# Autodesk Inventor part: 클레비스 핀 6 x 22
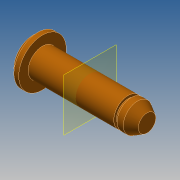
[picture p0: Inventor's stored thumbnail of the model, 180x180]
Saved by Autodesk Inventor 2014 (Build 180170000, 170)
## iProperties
IsCustomPart: 1
Created: 2017-08
Part Number: 클레비스 핀 6 x 22
Material: 강철
Description: 머리가 있는 클레비스 핀
Document SubType Name: Modeling
Standard: ISO 2341
Designer: mduedu
Standard Revision: Second edition 1986-11-01
Standards Organization: ISO
Language: ko-KR
Size Designation: B - 6 x 24
Categories: <MemberInstance><Categories><Category DisplayName="조임쇠" InternalName="e4da775c-781d-43d5-af7c-5136215cf5a6" Mnemonic="FSTN"><Category DisplayName="핀" InternalNa
Density: 7.85 g/cm^3
Appearance: 주황색
Author: mduedu
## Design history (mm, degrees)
sketch "스케치1"
  geometry: L1 (-2, 0)-(-2, 5); L2 (-2, 5)-(0, 5); L3 (0, 5)-(0, 3); L4 (0, 3)-(22, 3); L5 (22, 3)-(22, 0); L6 (-2, 0)-(22, 0); L7 (-7, 0)-(28, 0) reference; L8 (0, -1.96)-(0, 6.16) reference; C1 r 0.8 at (18.8, 0)
  constraints: 12 end point, 3 parallel, 2 collinear, 2 perpendicular, 1 centre point, 1 point on line, 1 vertical
  dimensions: "d0" = 6 diameter of L4 L6 (= NND); "d1" = 10 diameter of L2 L6 (= KOD); "d2" = 2 distance of L1.end L2.end (= KOH); "d3" = 22 distance of L3.end L4.end (= NLG); "d5" = 3.2 distance from line of L5 C1.centre (= DIST); "d6" = 1.6 diameter of C1 (= BOR)
revolve "본체" stored, may be unused: angle "d4" = 90 deg
workplane "Work Plane1"
node "작업 평면4"
sketch "스케치2"
  geometry: C1 r 3 at (0, 0) reference; C2 r 2.425 at (0, 0); 1 further point
  constraints: 1 centre point, 1 coincident
  dimensions: "d33" = 4.85 diameter of C2
extrude "돌출2" cut sketch "스케치2" distance "d34" = 0.7; taper "d35" = 0 deg
node "작업 평면5"
body "Solid1"
chamfer "모따기1" distance "d9" = 1 (= PHH2); stored, may be unused: angle "d10" = 45 deg (= FAWI2), second distance "d16" = 1 (= PHH2)
chamfer "모따기2" distance "d11" = 2 (= PHH1); stored, may be unused: angle "d12" = 30 deg (= FAWI1), second distance "d17" = 2 (= PHH1)
other parameters: "PHH1" = 2 [user parameter; used in 2 equation terms], "PHH2" = 1 [user parameter; used in 2 equation terms], "KOD" = 10 [user parameter; used in 1 equation term], "KOH" = 2 [user parameter; used in 1 equation term], "NND" = 6 [user parameter; used in 1 equation term], "FAWI1" = 30 deg [user parameter; used in 1 equation term], "FAWI2" = 45 deg [user parameter; used in 1 equation term], "DIST" = 3.2 [user parameter; used in 1 equation term], "BOR" = 1.6 [user parameter; used in 1 equation term], "NLG" = 22 [user parameter; used in 1 equation term], "d13" = 0, "d14" = 0, "d30" = 0, "d32" = 18
